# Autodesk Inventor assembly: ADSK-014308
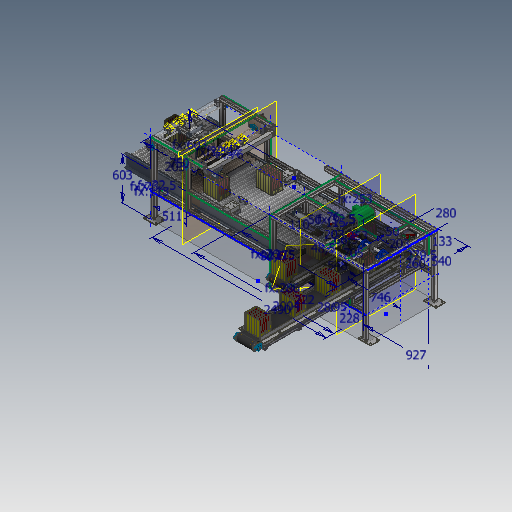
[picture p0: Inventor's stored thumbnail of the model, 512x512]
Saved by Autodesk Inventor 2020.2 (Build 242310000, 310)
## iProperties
Created: 2019-10
Part Number: ADSK-014308
Document SubType Name: Assembly
Designer: lutzd
Mass: 2.46905e+07 g
Surface Area: 565283 cm^2
Volume: 3.13993e+06 cm^3
Density: 7.8634 g/cm^3
VLDS_Profile: Default Assembly
VLDS_TimeStamp: 2016-07-29
VLDS_FailCnt: 0
VLDS_AcceptCnt: 0
Dimensions: 2553,4x1828,9x3579,9 mm
Mass: 24690,502 kg
DocNumber: ADSK-014308
Folder: 01 - Themengebiete\Simplification\01 - Packaging machine\
VDS_Category: 3D Komponenten
VDS_NumSchm: Autodesk
Title: MOD-039310
Author: lutzd
Revision Number: -
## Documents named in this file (30)
- D:\07 - DEMODATEN\OTX 2019 - Dataset - UPDATE - Dez2019\Designs\07-Packing machine\ADSK-014308.iam
- D:\07 - DEMODATEN\OTX 2019 - Dataset - UPDATE - Dez2019\Designs\07-Packing machine\ADSK-014261.iam
- D:\07 - DEMODATEN\OTX 2019 - Dataset - UPDATE - Dez2019\Designs\07-Packing machine\Parts\ADSK-011801.ipt
- D:\07 - DEMODATEN\OTX 2019 - Dataset - UPDATE - Dez2019\Content Center Files\de-DE\DIN 125-1  B\DIN 125-1 - B 13.ipt
- D:\07 - DEMODATEN\OTX 2019 - Dataset - UPDATE - Dez2019\Content Center Files\de-DE\ISO 4032(1)\ISO 4032 - M12DIN EN.ipt
- D:\07 - DEMODATEN\OTX 2019 - Dataset - UPDATE - Dez2019\Content Center Files\de-DE\ISO 4762(2)\ISO 4762 - M12 x 35ISO.ipt
- D:\07 - DEMODATEN\OTX 2019 - Dataset - UPDATE - Dez2019\Designs\07-Packing machine\SUB-319310.iam
- D:\07 - DEMODATEN\OTX 2019 - Dataset - UPDATE - Dez2019\Designs\07-Packing machine\Parts\ADSK-011638.ipt
- D:\07 - DEMODATEN\OTX 2019 - Dataset - UPDATE - Dez2019\Content Center Files\de-DE\ISO 4762(2)\ISO 4762 - M8 x 80ISO.ipt
- D:\07 - DEMODATEN\OTX 2019 - Dataset - UPDATE - Dez2019\Content Center Files\de-DE\DIN 125-1  B\DIN 125-1 - B 8,4.ipt
- D:\07 - DEMODATEN\OTX 2019 - Dataset - UPDATE - Dez2019\Content Center Files\de-DE\ISO 4762(2)\ISO 4762 - M8 x 20ISO.ipt
- D:\07 - DEMODATEN\OTX 2019 - Dataset - UPDATE - Dez2019\Content Center Files\de-DE\ISO 4762(2)\ISO 4762 - M8 x 25ISO.ipt
- D:\07 - DEMODATEN\OTX 2019 - Dataset - UPDATE - Dez2019\Designs\07-Packing machine\SUB-329310.iam
- D:\07 - DEMODATEN\OTX 2019 - Dataset - UPDATE - Dez2019\Content Center Files\de-DE\ISO 4762(2)\ISO 4762 - M8 x 16ISO.ipt
- D:\07 - DEMODATEN\OTX 2019 - Dataset - UPDATE - Dez2019\Designs\07-Packing machine\SUB-359310.iam
- D:\07 - DEMODATEN\OTX 2019 - Dataset - UPDATE - Dez2019\Designs\07-Packing machine\Parts\ADSK-011708.ipt
- D:\07 - DEMODATEN\OTX 2019 - Dataset - UPDATE - Dez2019\Designs\07-Packing machine\Parts\ADSK-011707.ipt
- D:\07 - DEMODATEN\OTX 2019 - Dataset - UPDATE - Dez2019\Designs\07-Packing machine\A102253.iam
- D:\07 - DEMODATEN\OTX 2019 - Dataset - UPDATE - Dez2019\Content Center Files\de-DE\DIN 125-1  B\DIN 125-1 - B 6,4.ipt
- D:\07 - DEMODATEN\OTX 2019 - Dataset - UPDATE - Dez2019\Content Center Files\de-DE\ISO 4032(1)\ISO 4032 - M6DIN EN.ipt
- D:\07 - DEMODATEN\OTX 2019 - Dataset - UPDATE - Dez2019\Content Center Files\de-DE\ISO 4762(2)\ISO 4762 - M6 x 60ISO.ipt
- D:\07 - DEMODATEN\OTX 2019 - Dataset - UPDATE - Dez2019\Designs\07-Packing machine\Parts\ADSK-011682.ipt
- D:\07 - DEMODATEN\OTX 2019 - Dataset - UPDATE - Dez2019\Content Center Files\de-DE\DIN 125-1  B\DIN 125-1 - B 10,5.ipt
- D:\07 - DEMODATEN\OTX 2019 - Dataset - UPDATE - Dez2019\Content Center Files\de-DE\ISO 4762(2)\ISO 4762 - M10 x 25ISO.ipt
- D:\07 - DEMODATEN\OTX 2019 - Dataset - UPDATE - Dez2019\Designs\07-Packing machine\A097170.iam
- D:\07 - DEMODATEN\OTX 2019 - Dataset - UPDATE - Dez2019\Designs\07-Packing machine\SUB-339310.iam
- D:\07 - DEMODATEN\OTX 2019 - Dataset - UPDATE - Dez2019\Content Center Files\de-DE\ISO 4032(1)\ISO 4032 - M8DIN EN.ipt
- D:\07 - DEMODATEN\OTX 2019 - Dataset - UPDATE - Dez2019\Content Center Files\de-DE\ISO 4762(2)\ISO 4762 - M8 x 35ISO.ipt
- D:\07 - DEMODATEN\OTX 2019 - Dataset - UPDATE - Dez2019\Designs\07-Packing machine\Parts\GMI 17 oz Pouch Tray.ipt
- GMI 17 oz Pouch Tray.ipt
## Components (171 placed, 28 different names)
1. ADSK-014261:1 [sub-assembly] — Passend:1, Fluchtend:2, Passend:18, Fluchtend:3, Fluchtend:4, Passend:20, Passend:21, Passend:40, Passend:41, Passend:42, Passend:47, Passend:48, Fluchtend:5, Passend:49, Fluchtend:6, Passend:50, Passend:59, Passend:60, Passend:61, Passend:62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
2. ADSK-011801:1 — Passend:1, Fluchtend:1, Fluchtend:2, Passend:19, Passend:152, Fluchtend:11, Passend:155, Passend:156, Passend:161, Fluchtend:12
3. SUB-319310:1 [sub-assembly] — Passend:19, Passend:20, Passend:21, Passend:22, Passend:162, Passend:164, Passend:165, Passend:169
4. ADSK-011638:1 — Passend:18, Fluchtend:3, Fluchtend:4, Passend:22
5. SUB-329310:1 [sub-assembly] — Passend:40, Passend:41, Passend:42, Passend:44, Passend:46, Einfügen:47, Einfügen:48
6. SUB-359310:1 [sub-assembly] — Passend:48, Fluchtend:5, Passend:49, Passend:61, Passend:62, Passend:153
7. SUB-359310:2 [sub-assembly] — Passend:47, Fluchtend:6, Passend:50, Passend:59, Passend:60, Passend:154, Passend:166
8. ADSK-011708:1 — Passend:63, Fluchtend:7, Fluchtend:8, Passend:68, Passend:71, Passend:72, Passend:74, Passend:76, Passend:78, Passend:80
9. ADSK-011707:1 — Passend:64, Passend:65, Passend:66, Passend:67, Passend:69, Passend:70, Passend:82, Passend:84
10. A102253:1 [sub-assembly] — Passend:67, Passend:69, Passend:70
11. A102253:2 [sub-assembly] — Passend:68, Passend:71, Passend:72, Passend:167
12. ADSK-011682:1 — Passend:101, Passend:102, Passend:103, Passend:108, Passend:109, Winkel:1
13. A097170:1 [sub-assembly] — Passend:108, Passend:109, Winkel:1
14. SUB-339310:1 [sub-assembly] — Passend:110, Passend:111, Passend:112, Passend:113, Passend:139, Passend:141, Passend:143, Passend:145, Passend:148, Passend:149, Fluchtend:9, Passend:150, Passend:151
15. GMI 17 oz Pouch Tray:17 — Passend:152, Fluchtend:11, Passend:153
16. GMI 17 oz Pouch Tray:19 — Passend:156, Passend:164, Passend:166
17. GMI 17 oz Pouch Tray:20 — Passend:155, Passend:169, Fluchtend:12
18. GMI 17 oz Pouch Tray:21 — Passend:159, Passend:167, Passend:168
19. GMI 17 oz Pouch Tray:22 — Passend:161, Passend:162, Passend:165, Passend:168
20. DIN 125-1 B B 8,4:29
21. DIN 125-1 B B 8,4:30 — Passend:131, Passend:133, Passend:135, Passend:137
22. DIN 125-1 B B 8,4:31
23. DIN 125-1 B B 8,4:32
24. DIN 125-1 B B 8,4:33 — Passend:123
25. DIN 125-1 B B 8,4:34 — Passend:125
26. DIN 125-1 B B 8,4:35 — Passend:127
27. DIN 125-1 B B 8,4:36 — Passend:129
28. DIN EN 24032 M8:1
29. DIN EN 24032 M8:2
30. DIN EN 24032 M8:3
31. DIN EN 24032 M8:4
32. ISO 4762 M8 x 35:1 — Passend:131
33. ISO 4762 M8 x 35:2 — Passend:133
34. ISO 4762 M8 x 35:3 — Passend:135
35. ISO 4762 M8 x 35:4 — Passend:137
36. DIN 125-1 B B 8,4:37 — Passend:139
37. DIN 125-1 B B 8,4:38 — Passend:141
38. DIN 125-1 B B 8,4:39 — Passend:143, Passend:147
39. DIN 125-1 B B 8,4:40 — Passend:145
40. ISO 4762 M8 x 20:13 — Passend:147
41. ISO 4762 M8 x 20:14
42. ISO 4762 M8 x 20:15
43. ISO 4762 M8 x 20:16
44. DIN 125-1 B B 10,5:1 — Passend:105, Passend:107
45. ISO 4762 M10 x 25:1 — Passend:107
46. DIN 125-1 B B 8,4:25 — Passend:119, Passend:121
47. DIN 125-1 B B 8,4:26
48. DIN 125-1 B B 8,4:27 — Passend:115, Passend:117
49. DIN 125-1 B B 8,4:28
50. ISO 4762 M8 x 20:9 — Passend:115
51. ISO 4762 M8 x 20:10 — Passend:117
52. ISO 4762 M8 x 20:11 — Passend:119
53. ISO 4762 M8 x 20:12 — Passend:121
54. DIN 125-1 B B 8,4:23 — Passend:98
55. DIN 125-1 B B 8,4:24 — Passend:100
56. ISO 4762 M8 x 16:15
57. ISO 4762 M8 x 16:16
58. DIN 125-1 B B 8,4:17 — Passend:74
59. DIN 125-1 B B 8,4:18 — Passend:76, Passend:90, Passend:92
60. DIN 125-1 B B 8,4:19 — Passend:78
61. DIN 125-1 B B 8,4:20 — Passend:80, Passend:94, Passend:96
62. DIN 125-1 B B 8,4:21 — Passend:82, Passend:86, Passend:88
63. DIN 125-1 B B 8,4:22 — Passend:84
64. ISO 4762 M8 x 16:9 — Passend:86
65. ISO 4762 M8 x 16:10 — Passend:88
66. ISO 4762 M8 x 16:11 — Passend:90
67. ISO 4762 M8 x 16:12 — Passend:92
68. ISO 4762 M8 x 16:13 — Passend:94
69. ISO 4762 M8 x 16:14 — Passend:96
70. DIN 125-1 B B 6,4:1
71. DIN 125-1 B B 6,4:2
72. DIN 125-1 B B 6,4:3
73. DIN 125-1 B B 6,4:4
74. DIN EN 24032 M6:1
75. DIN EN 24032 M6:2
76. DIN EN 24032 M6:3
77. DIN EN 24032 M6:4
78. DIN 125-1 B B 6,4:5
79. DIN 125-1 B B 6,4:6
80. DIN 125-1 B B 6,4:7
81. DIN 125-1 B B 6,4:8
82. DIN EN 24032 M6:5
83. DIN EN 24032 M6:6
84. DIN EN 24032 M6:7
85. DIN EN 24032 M6:8
86. ISO 4762 M6 x 60:1
87. ISO 4762 M6 x 60:2
88. ISO 4762 M6 x 60:3
89. ISO 4762 M6 x 60:4
90. ISO 4762 M6 x 60:5
91. ISO 4762 M6 x 60:6
92. ISO 4762 M6 x 60:7
93. ISO 4762 M6 x 60:8
94. DIN 125-1 B B 8,4:9 — Passend:44, Einfügen:47
95. DIN 125-1 B B 8,4:10 — Passend:46, Einfügen:48
96. ISO 4762 M8 x 16:1
97. ISO 4762 M8 x 16:2
98. DIN 125-1 B B 8,4:11
99. DIN 125-1 B B 8,4:12
100. ISO 4762 M8 x 16:3
101. ISO 4762 M8 x 16:4
102. DIN 125-1 B B 8,4:13 — Passend:56, Passend:58
103. DIN 125-1 B B 8,4:14
104. DIN 125-1 B B 8,4:15 — Passend:52, Passend:54
105. DIN 125-1 B B 8,4:16
106. ISO 4762 M8 x 16:5 — Passend:52
107. ISO 4762 M8 x 16:6 — Passend:54
108. ISO 4762 M8 x 16:7 — Passend:56
109. ISO 4762 M8 x 16:8 — Passend:58
110. ISO 4762 M8 x 80:1
111. ISO 4762 M8 x 80:2
112. ISO 4762 M8 x 80:3
113. ISO 4762 M8 x 80:4
114. ISO 4762 M8 x 80:5
115. ISO 4762 M8 x 80:6
116. ISO 4762 M8 x 80:7
117. ISO 4762 M8 x 80:8
118. DIN 125-1 B B 8,4:1
119. DIN 125-1 B B 8,4:2 — Passend:36, Passend:38
120. DIN 125-1 B B 8,4:3
121. DIN 125-1 B B 8,4:4 — Passend:32, Passend:34
122. DIN 125-1 B B 8,4:5 — Passend:28, Passend:30
123. DIN 125-1 B B 8,4:6
124. DIN 125-1 B B 8,4:7 — Passend:24, Passend:26
125. DIN 125-1 B B 8,4:8
126. ISO 4762 M8 x 20:1 — Passend:24
127. ISO 4762 M8 x 20:2 — Passend:26
128. ISO 4762 M8 x 20:3 — Passend:28
129. ISO 4762 M8 x 20:4 — Passend:30
130. ISO 4762 M8 x 25:1 — Passend:32
131. ISO 4762 M8 x 25:2 — Passend:34
132. ISO 4762 M8 x 20:7 — Passend:36
133. ISO 4762 M8 x 20:8 — Passend:38
134. DIN 125-1 B B 13:1
135. DIN 125-1 B B 13:2
136. DIN 125-1 B B 13:3
137. DIN 125-1 B B 13:4
138. DIN 125-1 B B 13:5
139. DIN 125-1 B B 13:6
140. DIN 125-1 B B 13:7
141. DIN 125-1 B B 13:8
142. DIN 125-1 B B 13:9
143. DIN 125-1 B B 13:10
144. DIN 125-1 B B 13:11
145. DIN 125-1 B B 13:12
146. DIN EN 24032 M12:1
147. DIN EN 24032 M12:2
148. DIN EN 24032 M12:3
149. DIN EN 24032 M12:4
150. DIN EN 24032 M12:5
151. DIN EN 24032 M12:6
152. DIN EN 24032 M12:7
153. DIN EN 24032 M12:8
154. DIN 125-1 B B 13:13
155. DIN 125-1 B B 13:14 — Passend:3, Passend:5, Passend:7, Passend:9, Passend:11, Passend:13, Passend:15, Passend:17
156. DIN 125-1 B B 13:15
157. DIN 125-1 B B 13:16
158. ISO 4762 M12 x 35:1 — Passend:3
159. ISO 4762 M12 x 35:2 — Passend:5
160. ISO 4762 M12 x 35:3 — Passend:7
161. ISO 4762 M12 x 35:4 — Passend:9
162. ISO 4762 M12 x 35:5 — Passend:11
163. ISO 4762 M12 x 35:6 — Passend:13
164. ISO 4762 M12 x 35:7 — Passend:15
165. ISO 4762 M12 x 35:8 — Passend:17
166. GMI 17 oz Pouch Tray:12 — Passend:148, Passend:149, Fluchtend:9
167. GMI 17 oz Pouch Tray:13
168. GMI 17 oz Pouch Tray:14
169. GMI 17 oz Pouch Tray:15
170. GMI 17 oz Pouch Tray:16 — Passend:151, Passend:154
171. GMI 17 oz Pouch Tray:18 — Passend:150
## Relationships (123: Mate 109, Flush 11, Insert 2, Angle 1)
- Passend:1 [Mate]: ADSK-014261:1 ↔ ADSK-011801:1
- Fluchtend:1 [Flush]: ADSK-011801:1
- Fluchtend:2 [Flush]: ADSK-014261:1 ↔ ADSK-011801:1
- Passend:3 [Mate]: DIN 125-1 B B 13:14 ↔ ISO 4762 M12 x 35:1
- Passend:5 [Mate]: DIN 125-1 B B 13:14 ↔ ISO 4762 M12 x 35:2
- Passend:7 [Mate]: DIN 125-1 B B 13:14 ↔ ISO 4762 M12 x 35:3
- Passend:9 [Mate]: DIN 125-1 B B 13:14 ↔ ISO 4762 M12 x 35:4
- Passend:11 [Mate]: DIN 125-1 B B 13:14 ↔ ISO 4762 M12 x 35:5
- Passend:13 [Mate]: DIN 125-1 B B 13:14 ↔ ISO 4762 M12 x 35:6
- Passend:15 [Mate]: DIN 125-1 B B 13:14 ↔ ISO 4762 M12 x 35:7
- Passend:17 [Mate]: DIN 125-1 B B 13:14 ↔ ISO 4762 M12 x 35:8
- Passend:18 [Mate]: ADSK-014261:1 ↔ ADSK-011638:1
- Fluchtend:3 [Flush]: ADSK-014261:1 ↔ ADSK-011638:1
- Fluchtend:4 [Flush]: ADSK-014261:1 ↔ ADSK-011638:1
- Passend:19 [Mate]: ADSK-011801:1 ↔ SUB-319310:1
- Passend:20 [Mate]: ADSK-014261:1 ↔ SUB-319310:1
- Passend:21 [Mate]: ADSK-014261:1 ↔ SUB-319310:1
- Passend:22 [Mate]: SUB-319310:1 ↔ ADSK-011638:1
- Passend:24 [Mate]: DIN 125-1 B B 8,4:7 ↔ ISO 4762 M8 x 20:1
- Passend:26 [Mate]: DIN 125-1 B B 8,4:7 ↔ ISO 4762 M8 x 20:2
- Passend:28 [Mate]: DIN 125-1 B B 8,4:5 ↔ ISO 4762 M8 x 20:3
- Passend:30 [Mate]: DIN 125-1 B B 8,4:5 ↔ ISO 4762 M8 x 20:4
- Passend:32 [Mate]: DIN 125-1 B B 8,4:4 ↔ ISO 4762 M8 x 25:1
- Passend:34 [Mate]: DIN 125-1 B B 8,4:4 ↔ ISO 4762 M8 x 25:2
- Passend:36 [Mate]: DIN 125-1 B B 8,4:2 ↔ ISO 4762 M8 x 20:7
- Passend:38 [Mate]: DIN 125-1 B B 8,4:2 ↔ ISO 4762 M8 x 20:8
- Passend:40 [Mate]: ADSK-014261:1 ↔ SUB-329310:1
- Passend:41 [Mate]: ADSK-014261:1 ↔ SUB-329310:1
- Passend:42 [Mate]: ADSK-014261:1 ↔ SUB-329310:1
- Passend:44 [Mate]: SUB-329310:1 ↔ DIN 125-1 B B 8,4:9
- Passend:46 [Mate]: SUB-329310:1 ↔ DIN 125-1 B B 8,4:10
- Einfügen:47 [Insert]: SUB-329310:1 ↔ DIN 125-1 B B 8,4:9
- Einfügen:48 [Insert]: SUB-329310:1 ↔ DIN 125-1 B B 8,4:10
- Passend:47 [Mate]: ADSK-014261:1 ↔ SUB-359310:2
- Passend:48 [Mate]: ADSK-014261:1 ↔ SUB-359310:1
- Fluchtend:5 [Flush]: ADSK-014261:1 ↔ SUB-359310:1
- Passend:49 [Mate]: ADSK-014261:1 ↔ SUB-359310:1
- Fluchtend:6 [Flush]: ADSK-014261:1 ↔ SUB-359310:2
- Passend:50 [Mate]: ADSK-014261:1 ↔ SUB-359310:2
- Passend:52 [Mate]: DIN 125-1 B B 8,4:15 ↔ ISO 4762 M8 x 16:5
- Passend:54 [Mate]: DIN 125-1 B B 8,4:15 ↔ ISO 4762 M8 x 16:6
- Passend:56 [Mate]: DIN 125-1 B B 8,4:13 ↔ ISO 4762 M8 x 16:7
- Passend:58 [Mate]: DIN 125-1 B B 8,4:13 ↔ ISO 4762 M8 x 16:8
- Passend:59 [Mate]: ADSK-014261:1 ↔ SUB-359310:2
- Passend:60 [Mate]: ADSK-014261:1 ↔ SUB-359310:2
- Passend:61 [Mate]: ADSK-014261:1 ↔ SUB-359310:1
- Passend:62 [Mate]: ADSK-014261:1 ↔ SUB-359310:1
- Passend:63 [Mate]: ADSK-014261:1 ↔ ADSK-011708:1
- Fluchtend:7 [Flush]: ADSK-014261:1 ↔ ADSK-011708:1
- Fluchtend:8 [Flush]: ADSK-014261:1 ↔ ADSK-011708:1
- Passend:64 [Mate]: ADSK-014261:1 ↔ ADSK-011707:1
- Passend:65 [Mate]: ADSK-014261:1 ↔ ADSK-011707:1
- Passend:66 [Mate]: ADSK-014261:1 ↔ ADSK-011707:1
- Passend:67 [Mate]: ADSK-011707:1 ↔ A102253:1
- Passend:68 [Mate]: ADSK-011708:1 ↔ A102253:2
- Passend:69 [Mate]: ADSK-011707:1 ↔ A102253:1
- Passend:70 [Mate]: ADSK-011707:1 ↔ A102253:1
- Passend:71 [Mate]: ADSK-011708:1 ↔ A102253:2
- Passend:72 [Mate]: ADSK-011708:1 ↔ A102253:2
- Passend:74 [Mate]: ADSK-011708:1 ↔ DIN 125-1 B B 8,4:17
- Passend:76 [Mate]: ADSK-011708:1 ↔ DIN 125-1 B B 8,4:18
- Passend:78 [Mate]: ADSK-011708:1 ↔ DIN 125-1 B B 8,4:19
- Passend:80 [Mate]: ADSK-011708:1 ↔ DIN 125-1 B B 8,4:20
- Passend:82 [Mate]: ADSK-011707:1 ↔ DIN 125-1 B B 8,4:21
- Passend:84 [Mate]: ADSK-011707:1 ↔ DIN 125-1 B B 8,4:22
- Passend:86 [Mate]: DIN 125-1 B B 8,4:21 ↔ ISO 4762 M8 x 16:9
- Passend:88 [Mate]: DIN 125-1 B B 8,4:21 ↔ ISO 4762 M8 x 16:10
- Passend:90 [Mate]: DIN 125-1 B B 8,4:18 ↔ ISO 4762 M8 x 16:11
- Passend:92 [Mate]: DIN 125-1 B B 8,4:18 ↔ ISO 4762 M8 x 16:12
- Passend:94 [Mate]: DIN 125-1 B B 8,4:20 ↔ ISO 4762 M8 x 16:13
- Passend:96 [Mate]: DIN 125-1 B B 8,4:20 ↔ ISO 4762 M8 x 16:14
- Passend:98 [Mate]: ADSK-014261:1 ↔ DIN 125-1 B B 8,4:23
- Passend:100 [Mate]: ADSK-014261:1 ↔ DIN 125-1 B B 8,4:24
- Passend:101 [Mate]: ADSK-014261:1 ↔ ADSK-011682:1
- Passend:102 [Mate]: ADSK-014261:1 ↔ ADSK-011682:1
- Passend:103 [Mate]: ADSK-014261:1 ↔ ADSK-011682:1
- Passend:105 [Mate]: ADSK-014261:1 ↔ DIN 125-1 B B 10,5:1
- Passend:107 [Mate]: DIN 125-1 B B 10,5:1 ↔ ISO 4762 M10 x 25:1
- Passend:108 [Mate]: ADSK-011682:1 ↔ A097170:1
- Passend:109 [Mate]: ADSK-011682:1 ↔ A097170:1
- Winkel:1 [Angle]: ADSK-011682:1 ↔ A097170:1
- Passend:110 [Mate]: ADSK-014261:1 ↔ SUB-339310:1
- Passend:111 [Mate]: ADSK-014261:1 ↔ SUB-339310:1
- Passend:112 [Mate]: ADSK-014261:1 ↔ SUB-339310:1
- Passend:113 [Mate]: ADSK-014261:1 ↔ SUB-339310:1
- Passend:115 [Mate]: DIN 125-1 B B 8,4:27 ↔ ISO 4762 M8 x 20:9
- Passend:117 [Mate]: DIN 125-1 B B 8,4:27 ↔ ISO 4762 M8 x 20:10
- Passend:119 [Mate]: DIN 125-1 B B 8,4:25 ↔ ISO 4762 M8 x 20:11
- Passend:121 [Mate]: DIN 125-1 B B 8,4:25 ↔ ISO 4762 M8 x 20:12
- Passend:123 [Mate]: ADSK-014261:1 ↔ DIN 125-1 B B 8,4:33
- Passend:125 [Mate]: ADSK-014261:1 ↔ DIN 125-1 B B 8,4:34
- Passend:127 [Mate]: ADSK-014261:1 ↔ DIN 125-1 B B 8,4:35
- Passend:129 [Mate]: ADSK-014261:1 ↔ DIN 125-1 B B 8,4:36
- Passend:131 [Mate]: DIN 125-1 B B 8,4:30 ↔ ISO 4762 M8 x 35:1
- Passend:133 [Mate]: DIN 125-1 B B 8,4:30 ↔ ISO 4762 M8 x 35:2
- Passend:135 [Mate]: DIN 125-1 B B 8,4:30 ↔ ISO 4762 M8 x 35:3
- Passend:137 [Mate]: DIN 125-1 B B 8,4:30 ↔ ISO 4762 M8 x 35:4
- Passend:139 [Mate]: SUB-339310:1 ↔ DIN 125-1 B B 8,4:37
- Passend:141 [Mate]: SUB-339310:1 ↔ DIN 125-1 B B 8,4:38
- Passend:143 [Mate]: SUB-339310:1 ↔ DIN 125-1 B B 8,4:39
- Passend:145 [Mate]: SUB-339310:1 ↔ DIN 125-1 B B 8,4:40
- Passend:147 [Mate]: DIN 125-1 B B 8,4:39 ↔ ISO 4762 M8 x 20:13
- Passend:148 [Mate]: SUB-339310:1 ↔ GMI 17 oz Pouch Tray:12
- Passend:149 [Mate]: SUB-339310:1 ↔ GMI 17 oz Pouch Tray:12
- Fluchtend:9 [Flush]: SUB-339310:1 ↔ GMI 17 oz Pouch Tray:12
- Passend:150 [Mate]: SUB-339310:1 ↔ GMI 17 oz Pouch Tray:18
- Passend:151 [Mate]: SUB-339310:1 ↔ GMI 17 oz Pouch Tray:16
- Passend:152 [Mate]: ADSK-011801:1 ↔ GMI 17 oz Pouch Tray:17
- Fluchtend:11 [Flush]: ADSK-011801:1 ↔ GMI 17 oz Pouch Tray:17
- Passend:153 [Mate]: SUB-359310:1 ↔ GMI 17 oz Pouch Tray:17
- Passend:154 [Mate]: SUB-359310:2 ↔ GMI 17 oz Pouch Tray:16
- Passend:155 [Mate]: ADSK-011801:1 ↔ GMI 17 oz Pouch Tray:20
- Passend:156 [Mate]: ADSK-011801:1 ↔ GMI 17 oz Pouch Tray:19
- Passend:159 [Mate]: ADSK-014261:1 ↔ GMI 17 oz Pouch Tray:21
- Passend:161 [Mate]: ADSK-011801:1 ↔ GMI 17 oz Pouch Tray:22
- Passend:162 [Mate]: SUB-319310:1 ↔ GMI 17 oz Pouch Tray:22
- Passend:164 [Mate]: SUB-319310:1 ↔ GMI 17 oz Pouch Tray:19
- Passend:165 [Mate]: SUB-319310:1 ↔ GMI 17 oz Pouch Tray:22
- Passend:166 [Mate]: SUB-359310:2 ↔ GMI 17 oz Pouch Tray:19
- Passend:167 [Mate]: A102253:2 ↔ GMI 17 oz Pouch Tray:21
- Passend:168 [Mate]: GMI 17 oz Pouch Tray:21 ↔ GMI 17 oz Pouch Tray:22
- Passend:169 [Mate]: SUB-319310:1 ↔ GMI 17 oz Pouch Tray:20
- Fluchtend:12 [Flush]: ADSK-011801:1 ↔ GMI 17 oz Pouch Tray:20
